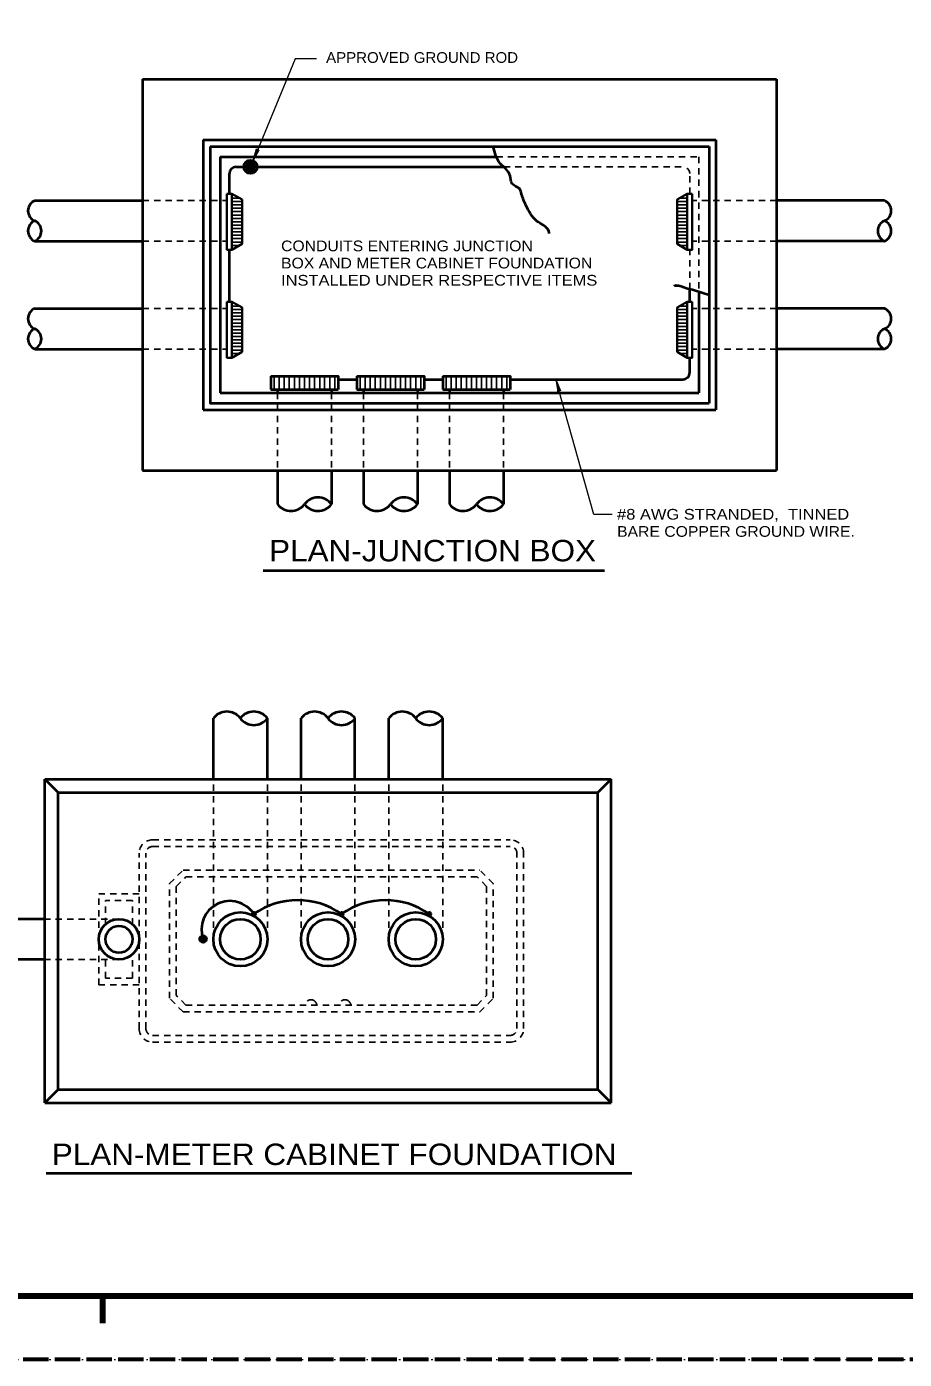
# Model space of a CAD drawing. Extents: x 312583 to 312854, y 144419 to 144597.
# Drawn here: x 312721.9 to 312784.3, y 144418.6 to 144513.2 of the extents above; entities that cross this region are included whole.
import ezdxf
from ezdxf.enums import TextEntityAlignment as Align

# ---------------------------------------------------------------- set-up
doc = ezdxf.new("R2010")
doc.units = 0
doc.header["$LTSCALE"] = 0.3
for name, pattern in [('DOTTED', [1.5, 0.3, -1.2]), ('LONG_DASHED', [7.5, 6, -1.5]), ('MEDIUM_DASHED', [4.5, 3, -1.5]), ('SHORT_DASHED', [2.7, 1.5, -1.2])]:
    doc.linetypes.add(name, pattern=pattern)
for name, color, linetype, lineweight in [('1', 7, 'Continuous', 25), ('2', 7, 'Continuous', 13), ('63', 7, 'DOTTED', 13)]:
    doc.layers.add(name, color=color, linetype=linetype, lineweight=lineweight)

msp = doc.modelspace()

# ---------------------------------------------------------------- linework, layer by layer
at = {"layer": '1', "lineweight": 40}
for p, q in [((312730.189, 144509.5006), (312775.2307, 144509.5006)), ((312730.189, 144509.5006), (312730.189, 144481.7089)), ((312775.2307, 144509.5006), (312775.2307, 144481.7089)), ((312734.4977, 144505.1919), (312734.4977, 144486.0252)), ((312734.4977, 144505.1919), (312770.9143, 144505.1919)), ((312770.9143, 144505.1919), (312770.9143, 144486.0252)), ((312734.9807, 144504.7089), (312770.439, 144504.7089)), ((312735.7013, 144503.9882), (312735.7013, 144487.2212)), ((312735.7013, 144503.9882), (312755.3357, 144503.9882)), ((312770.439, 144504.7089), (312770.439, 144486.5006)), ((312736.836, 144503.2752), (312755.8493, 144503.2752)), ((312736.3607, 144501.3586), (312736.3607, 144502.7922)), ((312722.5223, 144500.8756), (312730.189, 144500.8756)), ((312782.8973, 144500.8756), (312775.2307, 144500.8756)), ((312722.5223, 144498.0006), (312730.189, 144498.0006)), ((312736.3607, 144493.6919), (312736.3607, 144497.3872)), ((312782.8973, 144498.0006), (312775.2307, 144498.0006)), ((312769.059, 144493.6919), (312769.059, 144494.5812)), ((312769.7183, 144494.3896), (312769.7183, 144487.2212)), ((312722.5223, 144493.2089), (312730.189, 144493.2089)), ((312782.8973, 144493.2089), (312775.2307, 144493.2089)), ((312722.5223, 144490.3339), (312730.189, 144490.3339)), ((312782.8973, 144490.3339), (312775.2307, 144490.3339)), ((312769.059, 144488.6549), (312769.059, 144489.7206)), ((312739.2893, 144488.4172), (312739.2893, 144487.4589)), ((312744.081, 144488.1796), (312745.3997, 144488.1796)), ((312745.3997, 144488.4172), (312745.3997, 144487.4589)), ((312750.1913, 144488.1796), (312751.51, 144488.1796)), ((312751.51, 144488.4172), (312751.51, 144487.4589)), ((312756.3017, 144488.1796), (312768.5837, 144488.1796)), ((312735.7013, 144487.2212), (312769.7183, 144487.2212)), ((312739.2893, 144487.4589), (312744.081, 144487.4589)), ((312739.7723, 144487.4589), (312739.7723, 144487.2212)), ((312743.6057, 144487.4589), (312743.6057, 144487.2212)), ((312745.3997, 144487.4589), (312750.1913, 144487.4589)), ((312745.8827, 144487.4589), (312745.8827, 144487.2212)), ((312749.716, 144487.4589), (312749.716, 144487.2212)), ((312751.51, 144487.4589), (312756.3017, 144487.4589)), ((312751.993, 144487.4589), (312751.993, 144487.2212)), ((312755.8263, 144487.4589), (312755.8263, 144487.2212)), ((312734.4977, 144486.0252), (312770.9143, 144486.0252)), ((312730.189, 144481.7089), (312775.2307, 144481.7089)), ((312739.7723, 144481.7089), (312739.7723, 144479.3169)), ((312743.6057, 144481.7089), (312743.6057, 144479.3169)), ((312745.8827, 144481.7089), (312745.8827, 144479.3169)), ((312749.716, 144481.7089), (312749.716, 144479.3169)), ((312751.993, 144481.7089), (312751.993, 144479.3169)), ((312755.8263, 144481.7089), (312755.8263, 144479.3169)), ((312735.2183, 144459.7948), (312735.2183, 144464.1112)), ((312739.0516, 144459.7948), (312739.0516, 144464.1112)), ((312741.4436, 144459.7948), (312741.4436, 144464.1112)), ((312745.2769, 144459.7948), (312745.2769, 144464.1112)), ((312747.6766, 144459.7948), (312747.6766, 144464.1112)), ((312751.5099, 144459.7948), (312751.5099, 144464.1112)), ((312723.2353, 144459.7948), (312763.4853, 144459.7948)), ((312723.2353, 144436.7948), (312723.2353, 144459.7948)), ((312723.2353, 144459.7948), (312724.1936, 144458.8365)), ((312762.5269, 144458.8365), (312763.4853, 144459.7948)), ((312763.4853, 144436.7948), (312763.4853, 144459.7948)), ((312724.1936, 144458.8365), (312762.5269, 144458.8365)), ((312724.1936, 144437.7532), (312724.1936, 144458.8365)), ((312762.5269, 144437.7532), (312762.5269, 144458.8365)), ((312723.2353, 144449.8512), (312715.5686, 144449.8512)), ((312723.2353, 144446.9762), (312715.5686, 144446.9762)), ((312724.1936, 144437.7532), (312723.2353, 144436.7948)), ((312724.1936, 144437.7532), (312762.5269, 144437.7532)), ((312762.5269, 144437.7532), (312763.4853, 144436.7948)), ((312723.2353, 144436.7948), (312763.4853, 144436.7948))]:
    msp.add_line(p, q, dxfattribs=at)
at = {"layer": '1', "linetype": 'SHORT_DASHED'}
for p, q in [((312755.3357, 144503.9882), (312769.7183, 144503.9882)), ((312769.7183, 144503.9882), (312769.7183, 144494.3896)), ((312755.8493, 144503.2752), (312768.5837, 144503.2752)), ((312769.059, 144501.3586), (312769.059, 144502.7922)), ((312769.059, 144494.5812), (312769.059, 144497.3872)), ((312735.2183, 144448.4175), (312735.2183, 144459.7948)), ((312739.0516, 144448.4175), (312739.0516, 144459.7948)), ((312741.4436, 144448.4175), (312741.4436, 144459.7948)), ((312745.2769, 144448.4175), (312745.2769, 144459.7948)), ((312747.6766, 144448.4175), (312747.6766, 144459.7948)), ((312751.5099, 144448.4175), (312751.5099, 144459.7948)), ((312730.9019, 144455.4862), (312756.3016, 144455.4862)), ((312730.9019, 144455.0032), (312756.3016, 144455.0032)), ((312729.9436, 144442.0695), (312729.9436, 144454.5278)), ((312730.4266, 144442.0695), (312730.4266, 144454.5278)), ((312756.7769, 144442.0695), (312756.7769, 144454.5278)), ((312757.2599, 144442.0695), (312757.2599, 144454.5278)), ((312732.1056, 144452.3735), (312733.0639, 144453.3318)), ((312732.5809, 144452.1742), (312733.2633, 144452.8488)), ((312733.0639, 144453.3318), (312754.1473, 144453.3318)), ((312733.2633, 144452.8488), (312753.9479, 144452.8488)), ((312754.6226, 144452.1742), (312753.9479, 144452.8488)), ((312755.1056, 144452.3735), (312754.1473, 144453.3318)), ((312732.1056, 144444.2238), (312732.1056, 144452.3735)), ((312732.5809, 144444.4232), (312732.5809, 144452.1742)), ((312754.6226, 144444.4232), (312754.6226, 144452.1742)), ((312755.1056, 144444.2238), (312755.1056, 144452.3735)), ((312727.0686, 144445.1822), (312727.0686, 144451.6528)), ((312729.9436, 144451.6528), (312727.0686, 144451.6528)), ((312729.4683, 144451.1698), (312727.5516, 144451.1698)), ((312727.5516, 144449.4908), (312727.5516, 144451.1698)), ((312729.4683, 144449.4755), (312729.4683, 144451.1698)), ((312728.5099, 144449.8512), (312723.2353, 144449.8512)), ((312727.5516, 144445.6652), (312727.5516, 144447.3442)), ((312729.4683, 144445.6652), (312729.4683, 144447.2905)), ((312728.5099, 144446.9762), (312723.2353, 144446.9762)), ((312729.4683, 144445.6652), (312727.5516, 144445.6652)), ((312729.9436, 144445.1822), (312727.0686, 144445.1822)), ((312733.2633, 144443.7485), (312732.5809, 144444.4232)), ((312753.9479, 144443.7485), (312754.6226, 144444.4232)), ((312733.0639, 144443.2655), (312732.1056, 144444.2238)), ((312733.2633, 144443.7485), (312753.9479, 144443.7485)), ((312754.1473, 144443.2655), (312755.1056, 144444.2238)), ((312733.0639, 144443.2655), (312754.1473, 144443.2655)), ((312730.9019, 144441.5865), (312756.3016, 144441.5865)), ((312730.9019, 144441.1112), (312756.3016, 144441.1112))]:
    msp.add_line(p, q, dxfattribs=at)
at = {"layer": '1', "lineweight": 35}
for p, q in [((312736.537, 144501.3586), (312736.1767, 144501.3586)), ((312736.537, 144497.3872), (312736.537, 144501.3586)), ((312768.8827, 144497.3872), (312768.8827, 144501.3586)), ((312768.8827, 144501.3586), (312769.243, 144501.3586)), ((312737.25, 144497.8012), (312736.537, 144497.3872)), ((312768.1697, 144497.8012), (312768.8827, 144497.3872)), ((312736.537, 144493.6919), (312736.1767, 144493.6919)), ((312736.537, 144489.7206), (312736.537, 144493.6919)), ((312768.8827, 144489.7206), (312768.8827, 144493.6919)), ((312768.8827, 144493.6919), (312769.243, 144493.6919)), ((312737.25, 144490.1346), (312736.537, 144489.7206)), ((312768.1697, 144490.1346), (312768.8827, 144489.7206))]:
    msp.add_line(p, q, dxfattribs=at)
at = {"layer": '1'}
for p, q in [((312736.537, 144501.0519), (312737.066, 144501.0519)), ((312736.537, 144500.8066), (312737.25, 144500.8066)), ((312736.537, 144500.5689), (312737.25, 144500.5689)), ((312736.537, 144500.3312), (312737.25, 144500.3312)), ((312768.8827, 144500.8066), (312768.1697, 144500.8066)), ((312768.8827, 144500.5689), (312768.1697, 144500.5689)), ((312768.8827, 144500.3312), (312768.1697, 144500.3312)), ((312768.8827, 144501.0519), (312768.346, 144501.0519)), ((312736.537, 144500.0936), (312737.25, 144500.0936)), ((312736.537, 144499.8482), (312737.25, 144499.8482)), ((312736.537, 144499.6106), (312737.25, 144499.6106)), ((312736.537, 144499.3729), (312737.25, 144499.3729)), ((312768.8827, 144500.0936), (312768.1697, 144500.0936)), ((312768.8827, 144499.8482), (312768.1697, 144499.8482)), ((312768.8827, 144499.6106), (312768.1697, 144499.6106)), ((312768.8827, 144499.3729), (312768.1697, 144499.3729)), ((312736.537, 144499.1352), (312737.25, 144499.1352)), ((312736.537, 144498.8899), (312737.25, 144498.8899)), ((312736.537, 144498.6522), (312737.25, 144498.6522)), ((312736.537, 144498.4146), (312737.25, 144498.4146)), ((312768.8827, 144499.1352), (312768.1697, 144499.1352)), ((312768.8827, 144498.8899), (312768.1697, 144498.8899)), ((312768.8827, 144498.6522), (312768.1697, 144498.6522)), ((312768.8827, 144498.4146), (312768.1697, 144498.4146)), ((312736.537, 144498.1769), (312737.25, 144498.1769)), ((312736.537, 144497.9316), (312737.25, 144497.9316)), ((312736.537, 144497.6939), (312737.066, 144497.6939)), ((312768.8827, 144498.1769), (312768.1697, 144498.1769)), ((312768.8827, 144497.9316), (312768.1697, 144497.9316)), ((312768.8827, 144497.6939), (312768.346, 144497.6939)), ((312736.537, 144493.3852), (312737.066, 144493.3852)), ((312736.537, 144493.1399), (312737.25, 144493.1399)), ((312736.537, 144492.9022), (312737.25, 144492.9022)), ((312736.537, 144492.6646), (312737.25, 144492.6646)), ((312768.8827, 144493.1399), (312768.1697, 144493.1399)), ((312768.8827, 144492.9022), (312768.1697, 144492.9022)), ((312768.8827, 144492.6646), (312768.1697, 144492.6646)), ((312768.8827, 144493.3852), (312768.346, 144493.3852)), ((312736.537, 144492.4269), (312737.25, 144492.4269)), ((312736.537, 144492.1816), (312737.25, 144492.1816)), ((312736.537, 144491.9439), (312737.25, 144491.9439)), ((312736.537, 144491.7062), (312737.25, 144491.7062)), ((312768.8827, 144492.4269), (312768.1697, 144492.4269)), ((312768.8827, 144492.1816), (312768.1697, 144492.1816)), ((312768.8827, 144491.9439), (312768.1697, 144491.9439)), ((312768.8827, 144491.7062), (312768.1697, 144491.7062)), ((312736.537, 144491.4686), (312737.25, 144491.4686)), ((312736.537, 144491.2232), (312737.25, 144491.2232)), ((312736.537, 144490.9856), (312737.25, 144490.9856)), ((312736.537, 144490.7479), (312737.25, 144490.7479)), ((312768.8827, 144491.4686), (312768.1697, 144491.4686)), ((312768.8827, 144491.2232), (312768.1697, 144491.2232)), ((312768.8827, 144490.9856), (312768.1697, 144490.9856)), ((312768.8827, 144490.7479), (312768.1697, 144490.7479)), ((312736.537, 144490.5102), (312737.25, 144490.5102)), ((312736.537, 144490.2649), (312737.25, 144490.2649)), ((312736.537, 144490.0272), (312737.066, 144490.0272)), ((312768.8827, 144490.5102), (312768.1697, 144490.5102)), ((312768.8827, 144490.2649), (312768.1697, 144490.2649)), ((312768.8827, 144490.0272), (312768.346, 144490.0272)), ((312739.5347, 144487.4589), (312739.5347, 144488.4172)), ((312739.895, 144487.4589), (312739.895, 144488.4172)), ((312740.2477, 144487.4589), (312740.2477, 144488.4172)), ((312740.608, 144487.4589), (312740.608, 144488.4172)), ((312740.9683, 144487.4589), (312740.9683, 144488.4172)), ((312741.3287, 144487.4589), (312741.3287, 144488.4172)), ((312741.689, 144487.4589), (312741.689, 144488.4172)), ((312742.0493, 144487.4589), (312742.0493, 144488.4172)), ((312742.4097, 144487.4589), (312742.4097, 144488.4172)), ((312742.77, 144487.4589), (312742.77, 144488.4172)), ((312743.1227, 144487.4589), (312743.1227, 144488.4172)), ((312743.483, 144487.4589), (312743.483, 144488.4172)), ((312743.8433, 144487.4589), (312743.8433, 144488.4172)), ((312745.645, 144487.4589), (312745.645, 144488.4172)), ((312745.9977, 144487.4589), (312745.9977, 144488.4172)), ((312746.358, 144487.4589), (312746.358, 144488.4172)), ((312746.7183, 144487.4589), (312746.7183, 144488.4172)), ((312747.0787, 144487.4589), (312747.0787, 144488.4172)), ((312747.439, 144487.4589), (312747.439, 144488.4172)), ((312747.7993, 144487.4589), (312747.7993, 144488.4172)), ((312748.1597, 144487.4589), (312748.1597, 144488.4172)), ((312748.52, 144487.4589), (312748.52, 144488.4172)), ((312748.8727, 144487.4589), (312748.8727, 144488.4172)), ((312749.233, 144487.4589), (312749.233, 144488.4172)), ((312749.5933, 144487.4589), (312749.5933, 144488.4172)), ((312749.9537, 144487.4589), (312749.9537, 144488.4172)), ((312751.7477, 144487.4589), (312751.7477, 144488.4172)), ((312752.108, 144487.4589), (312752.108, 144488.4172)), ((312752.4683, 144487.4589), (312752.4683, 144488.4172)), ((312752.8287, 144487.4589), (312752.8287, 144488.4172)), ((312753.189, 144487.4589), (312753.189, 144488.4172)), ((312753.5493, 144487.4589), (312753.5493, 144488.4172)), ((312753.9097, 144487.4589), (312753.9097, 144488.4172)), ((312754.27, 144487.4589), (312754.27, 144488.4172)), ((312754.6227, 144487.4589), (312754.6227, 144488.4172)), ((312754.983, 144487.4589), (312754.983, 144488.4172)), ((312755.3433, 144487.4589), (312755.3433, 144488.4172)), ((312755.7037, 144487.4589), (312755.7037, 144488.4172)), ((312756.064, 144487.4589), (312756.064, 144488.4172))]:
    msp.add_line(p, q, dxfattribs=at)
at = {"layer": '1', "lineweight": 158}
for p, q in [((312616.5, 144423.0846), (312849, 144423.0846)), ((312727.35, 144421.1646), (312727.35, 144423.0846))]:
    msp.add_line(p, q, dxfattribs=at)
at = {"layer": '1', "linetype": 'LONG_DASHED', "lineweight": 60}
msp.add_line((312851.75, 144418.5846), (312583.526, 144418.5846), dxfattribs=at)
at = {"layer": '1', "lineweight": 40}
for points in [[(312734.9807, 144504.7089), (312734.9807, 144486.5006), (312770.439, 144486.5006)], [(312739.2893, 144488.4172), (312744.081, 144488.4172), (312744.081, 144487.4589)], [(312745.3997, 144488.4172), (312750.1913, 144488.4172), (312750.1913, 144487.4589)], [(312751.51, 144488.4172), (312756.3017, 144488.4172), (312756.3017, 144487.4589)]]:
    msp.add_lwpolyline(points, dxfattribs=at)
at = {"layer": '1', "lineweight": 35}
for points in [[(312736.537, 144497.3872), (312736.1767, 144497.3872), (312736.1767, 144501.3586)], [(312737.25, 144497.8012), (312737.25, 144500.9446), (312736.537, 144501.3586)], [(312768.1697, 144497.8012), (312768.1697, 144500.9446), (312768.8827, 144501.3586)], [(312768.8827, 144497.3872), (312769.243, 144497.3872), (312769.243, 144501.3586)], [(312736.537, 144489.7206), (312736.1767, 144489.7206), (312736.1767, 144493.6919)], [(312737.25, 144490.1346), (312737.25, 144493.2779), (312736.537, 144493.6919)], [(312768.1697, 144490.1346), (312768.1697, 144493.2779), (312768.8827, 144493.6919)], [(312768.8827, 144489.7206), (312769.243, 144489.7206), (312769.243, 144493.6919)]]:
    msp.add_lwpolyline(points, dxfattribs=at)
at = {"layer": '1', "lineweight": 40}
for centre, radius in [((312737.8547, 144503.2724), 0.4792), ((312737.8547, 144503.2724), 0.3594), ((312737.8547, 144503.2724), 0.2695), ((312737.8547, 144503.2724), 0.2021), ((312737.8547, 144503.2724), 0.1516), ((312737.8547, 144503.2724), 0.1137), ((312737.8547, 144503.2724), 0.0853), ((312737.8547, 144503.2724), 0.064), ((312737.8547, 144503.2724), 0.00884), ((312737.134, 144448.4175), 1.9167), ((312738.0947, 144450.2125), 0.1198), ((312738.0948, 144450.2125), 0.0898), ((312738.0949, 144450.2125), 0.0599), ((312738.0951, 144450.2125), 0.03), ((312738.0952, 144450.2129), 0.00409), ((312743.3631, 144448.4175), 1.9167), ((312744.3239, 144450.2125), 0.1198), ((312744.324, 144450.2125), 0.0898), ((312744.3241, 144450.2125), 0.0599), ((312744.3242, 144450.2125), 0.03), ((312744.3244, 144450.2129), 0.00409), ((312749.5923, 144448.4175), 1.9167), ((312750.553, 144450.2125), 0.1198), ((312750.5532, 144450.2125), 0.0898), ((312750.5533, 144450.2125), 0.0599), ((312750.5534, 144450.2125), 0.03), ((312750.5535, 144450.2129), 0.00409), ((312728.509, 144448.4175), 1.4375), ((312728.509, 144448.4175), 0.9583), ((312737.134, 144448.4175), 1.4375), ((312743.3631, 144448.4175), 1.4375), ((312749.5923, 144448.4175), 1.4375), ((312734.4832, 144448.4357), 0.2396), ((312734.4835, 144448.4357), 0.1797), ((312734.4837, 144448.4357), 0.1198), ((312734.4839, 144448.4357), 0.0599), ((312734.4842, 144448.4367), 0.00819)]:
    msp.add_circle(centre, radius, dxfattribs=at)
for centre, radius, start, end in [((312736.837, 144502.7932), 0.4792, 90, 180), ((312722.8209, 144500.1578), 0.7786, 112.61987, 247.38014), ((312782.5969, 144500.1578), 0.7786, 292.61986, 67.38013), ((312722.8209, 144498.7203), 0.7786, 112.61986, 247.38013), ((312722.2219, 144498.7203), 0.7786, 292.61986, 67.38013), ((312783.1959, 144498.7203), 0.7786, 112.61987, 247.38014), ((312782.5969, 144498.7203), 0.7786, 292.61987, 67.38014), ((312722.8209, 144492.4911), 0.7786, 112.61987, 247.38014), ((312782.5969, 144492.4911), 0.7786, 292.61986, 67.38013), ((312722.8209, 144491.0536), 0.7786, 112.61986, 247.38013), ((312722.2219, 144491.0536), 0.7786, 292.61986, 67.38013), ((312783.1959, 144491.0536), 0.7786, 112.61987, 247.38014), ((312782.5969, 144491.0536), 0.7786, 292.61987, 67.38014), ((312768.5808, 144488.6578), 0.4792, 270, 0), ((312742.6464, 144478.5953), 1.1979, 36.8699, 143.1301), ((312748.7558, 144478.5953), 1.1979, 36.8699, 143.1301), ((312754.8651, 144478.5953), 1.1979, 36.8699, 143.1301), ((312740.7297, 144480.0328), 1.1979, 216.8699, 323.1301), ((312742.6464, 144480.0328), 1.1979, 216.8699, 323.1301), ((312746.8391, 144480.0328), 1.1979, 216.8699, 323.1301), ((312748.7558, 144480.0328), 1.1979, 216.8699, 323.1301), ((312752.9485, 144480.0328), 1.1979, 216.8699, 323.1301), ((312754.8651, 144480.0328), 1.1979, 216.8699, 323.1301), ((312736.3951, 144449.1088), 2.0269, 32.99106, 199.3948), ((312741.2098, 144445.7688), 5.4264, 54.97291, 125.02709), ((312747.4389, 144445.7688), 5.4264, 54.97291, 125.02709)]:
    msp.add_arc(centre, radius, start, end, dxfattribs=at)
at = {"layer": '1', "linetype": 'SHORT_DASHED'}
for centre, radius, start, end in [((312768.5808, 144502.7932), 0.4792, 0, 90), ((312730.9048, 144454.5269), 0.9583, 90, 180), ((312730.9048, 144454.5269), 0.4792, 90, 180), ((312756.3006, 144454.5269), 0.9583, 0, 90), ((312756.3006, 144454.5269), 0.4792, 0, 90), ((312730.9048, 144442.0685), 0.9583, 180, 270), ((312730.9048, 144442.0685), 0.4792, 180, 270), ((312756.3006, 144442.0685), 0.9583, 270, 0), ((312756.3006, 144442.0685), 0.4792, 270, 0)]:
    msp.add_arc(centre, radius, start, end, dxfattribs=at)
at = {"layer": '1', "lineweight": 40}
for points in [[(312759.077, 144498.5296), (312759.0463, 144498.6982), (312758.203, 144499.4266), (312757.444, 144500.5152), (312757.1143, 144501.3356), (312756.961, 144501.7266), (312756.4473, 144502.0639), (312756.386, 144502.2096), (312756.2633, 144502.7539), (312755.8723, 144503.2446), (312755.5963, 144503.5129), (312755.1057, 144504.7089)], [(312770.439, 144494.1672), (312769.2507, 144494.5276), (312768.8213, 144494.6426), (312768.07, 144494.8266), (312768.0393, 144494.8266), (312767.978, 144494.9032)]]:
    msp.add_spline(points, degree=3, dxfattribs=at)
at = {"layer": '2'}
for p, q in [((312738.0397, 144503.7122), (312738.2697, 144504.5556)), ((312738.0397, 144503.7122), (312738.469, 144504.4712)), ((312738.2697, 144504.5556), (312738.262, 144504.2566)), ((312738.469, 144504.4712), (312738.262, 144504.2566)), ((312759.5523, 144488.1796), (312759.6827, 144487.3132)), ((312759.5523, 144488.1796), (312759.8897, 144487.3746)), ((312759.6827, 144487.3132), (312759.7133, 144487.6122)), ((312759.8897, 144487.3746), (312759.7133, 144487.6122))]:
    msp.add_line(p, q, dxfattribs=at)
at = {"layer": '2', "linetype": 'SHORT_DASHED', "lineweight": 25}
for p, q in [((312730.189, 144500.8756), (312736.1767, 144500.8756)), ((312775.2307, 144500.8756), (312769.243, 144500.8756)), ((312730.189, 144498.0006), (312736.1767, 144498.0006)), ((312775.2307, 144498.0006), (312769.243, 144498.0006)), ((312730.189, 144493.2089), (312736.1767, 144493.2089)), ((312775.2307, 144493.2089), (312769.243, 144493.2089)), ((312730.189, 144490.3339), (312736.1767, 144490.3339)), ((312775.2307, 144490.3339), (312769.243, 144490.3339)), ((312739.7723, 144487.2212), (312739.7723, 144481.7089)), ((312743.6057, 144487.2212), (312743.6057, 144481.7089)), ((312745.8827, 144487.2212), (312745.8827, 144481.7089)), ((312749.716, 144487.2212), (312749.716, 144481.7089)), ((312751.993, 144487.2212), (312751.993, 144481.7089)), ((312755.8263, 144487.2212), (312755.8263, 144481.7089))]:
    msp.add_line(p, q, dxfattribs=at)
at = {"layer": '2', "lineweight": 40}
for p, q in [((312738.7591, 144474.5988), (312762.9975, 144474.5988)), ((312723.3473, 144431.8115), (312764.9588, 144431.8115))]:
    msp.add_line(p, q, dxfattribs=at)
at = {"layer": '2'}
for points in [[(312742.54, 144510.9496), (312741.0373, 144510.9496), (312738.0397, 144503.7122)], [(312763.539, 144478.5809), (312762.2587, 144478.5809), (312759.5523, 144488.1796)]]:
    msp.add_lwpolyline(points, dxfattribs=at)
at = {"layer": '2', "lineweight": 40}
for centre, start, end in [((312736.1756, 144463.3915), 36.8699, 143.1301), ((312738.0923, 144463.3915), 36.8699, 143.1301), ((312742.4048, 144463.3915), 36.8699, 143.1301), ((312744.3215, 144463.3915), 36.8699, 143.1301), ((312748.634, 144463.3915), 36.8699, 143.1301), ((312750.5506, 144463.3915), 36.8699, 143.1301), ((312738.0923, 144464.829), 216.8699, 323.1301), ((312744.3215, 144464.829), 216.8699, 323.1301), ((312750.5506, 144464.829), 216.8699, 323.1301)]:
    msp.add_arc(centre, 1.1979, start, end, dxfattribs=at)
at = {"layer": '2', "linetype": 'MEDIUM_DASHED', "lineweight": 25}
for centre, start, end in [((312742.1566, 144443.7142), 4.42226, 175.58189), ((312744.5697, 144443.7142), 4.41811, 175.57774)]:
    msp.add_arc(centre, 0.4081, start, end, dxfattribs=at)
at = {"layer": '63'}
msp.add_lwpolyline([(312601.2, 144418.5846), (312853.5, 144418.5846), (312853.5, 144596.7846)], dxfattribs=at)

# ---------------------------------------------------------------- texts
at = {"layer": '2'}
for s, width, p in [('APPROVED GROUND ROD', 1.05, (312743.2269, 144510.6582)), ('CONDUITS ENTERING JUNCTION', 1.1, (312740.0253, 144497.2789)), ('BOX AND METER CABINET FOUNDATION', 1.1, (312740.0253, 144496.0589)), ('INSTALLED UNDER RESPECTIVE ITEMS', 1.15, (312740.0253, 144494.8389)), ('#8 AWG STRANDED,  TINNED', 1.15, (312763.8993, 144478.2196)), ('BARE COPPER GROUND WIRE.', 1.1, (312763.8993, 144476.9996))]:
    msp.add_text(s, height=0.76, dxfattribs=dict(at, width=width)).set_placement(p)
at = {"layer": '2', "width": 1.1}
for s, p in [('PLAN-JUNCTION BOX', (312750.789, 144475.2566)), ('PLAN-METER CABINET FOUNDATION', (312743.7989, 144432.3849))]:
    msp.add_text(s, height=1.52, dxfattribs=at).set_placement(p, align=Align.CENTER)

doc.saveas('drawing.dxf')
